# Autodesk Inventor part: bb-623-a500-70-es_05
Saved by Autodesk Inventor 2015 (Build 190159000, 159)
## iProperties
Created: 2022-04
Part Number: bb-623-a500-70-es_05
Checked By: TraceParts S.A.
Material: Generic
Catalog Web Link: www.traceparts.com
Document SubType Name: Modeling
Designer: TraceParts
Density: 1 g/cm^3
Appearance: Default
Company: TraceParts S.A.
Author: TraceParts
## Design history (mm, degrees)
feature "bb-623-a500-70-es_05.ipt"
body "Solid1"
